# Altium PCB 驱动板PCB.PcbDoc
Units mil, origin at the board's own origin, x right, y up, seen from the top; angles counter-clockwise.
Board outline 3955.03 x 2772.03 mil, 2 copper layers (Top Layer, Bottom Layer); 5 components, 29 nets, 126 pads, 119 vias.
Unrouted connection lines stored in the file: 15.
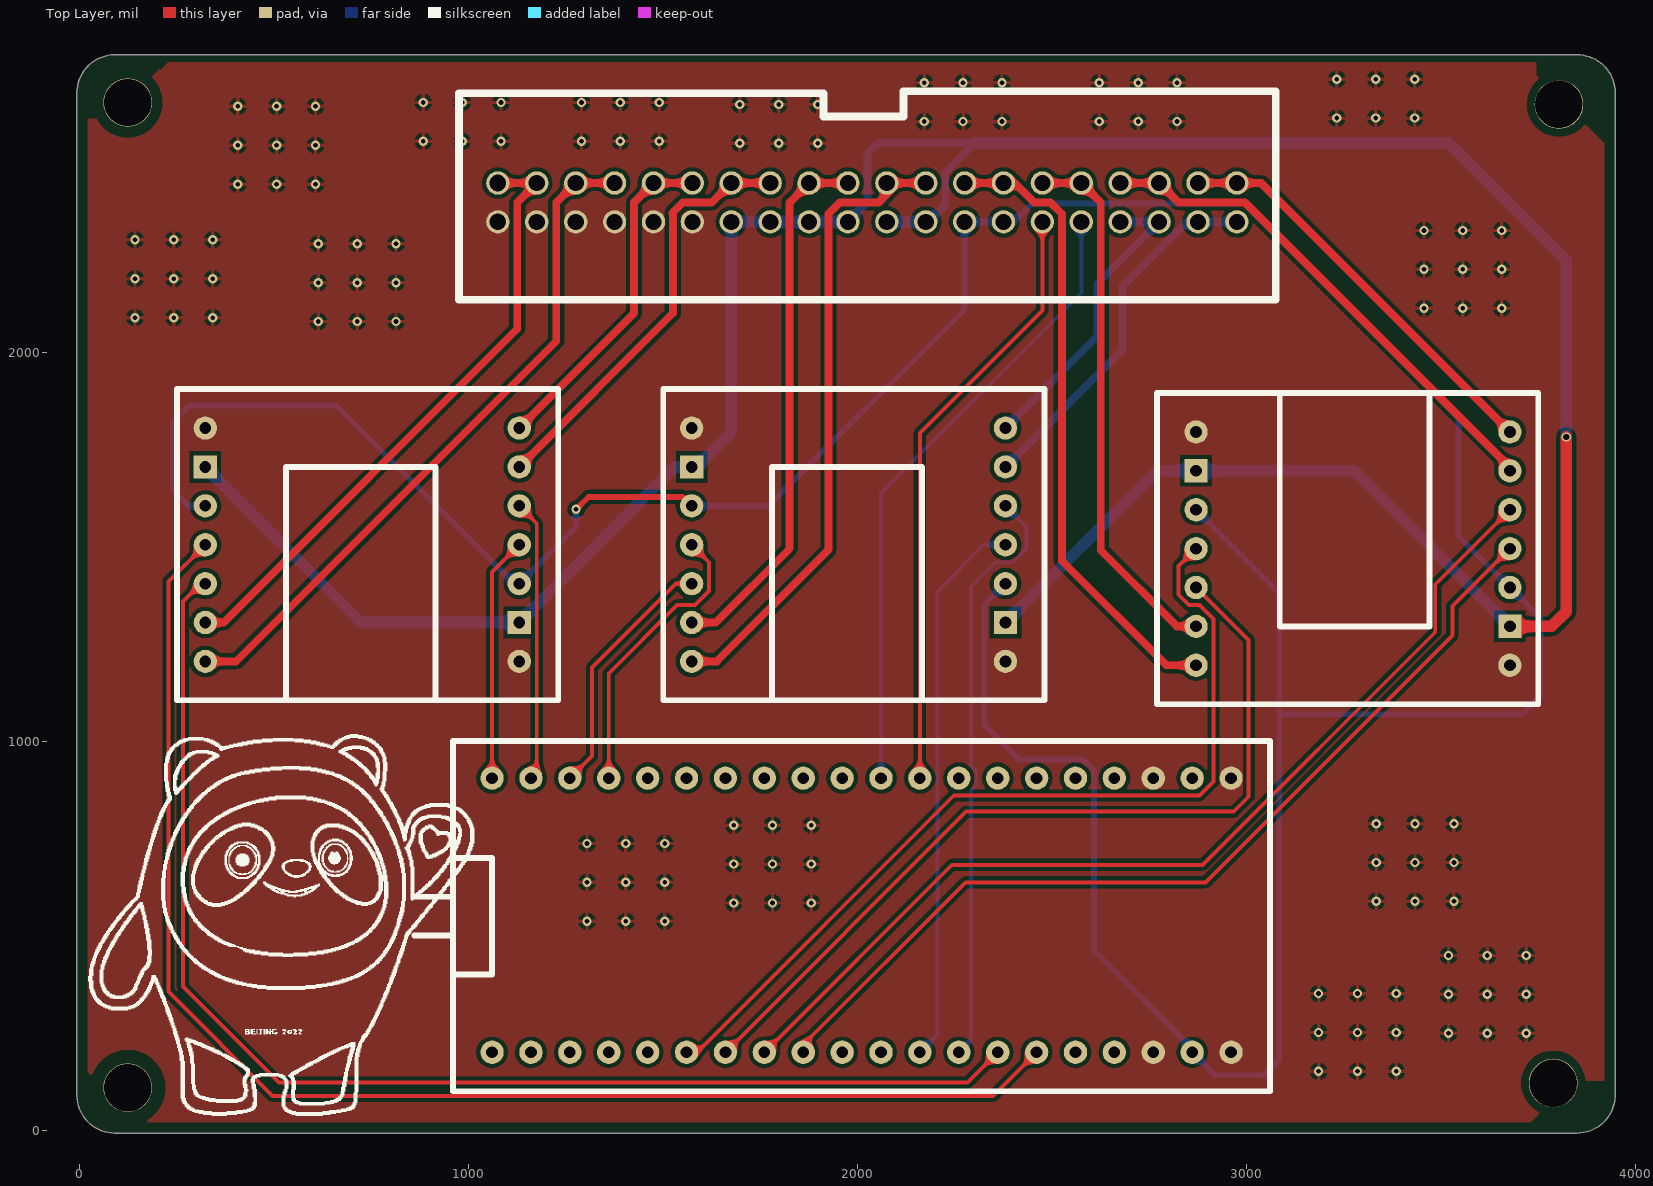
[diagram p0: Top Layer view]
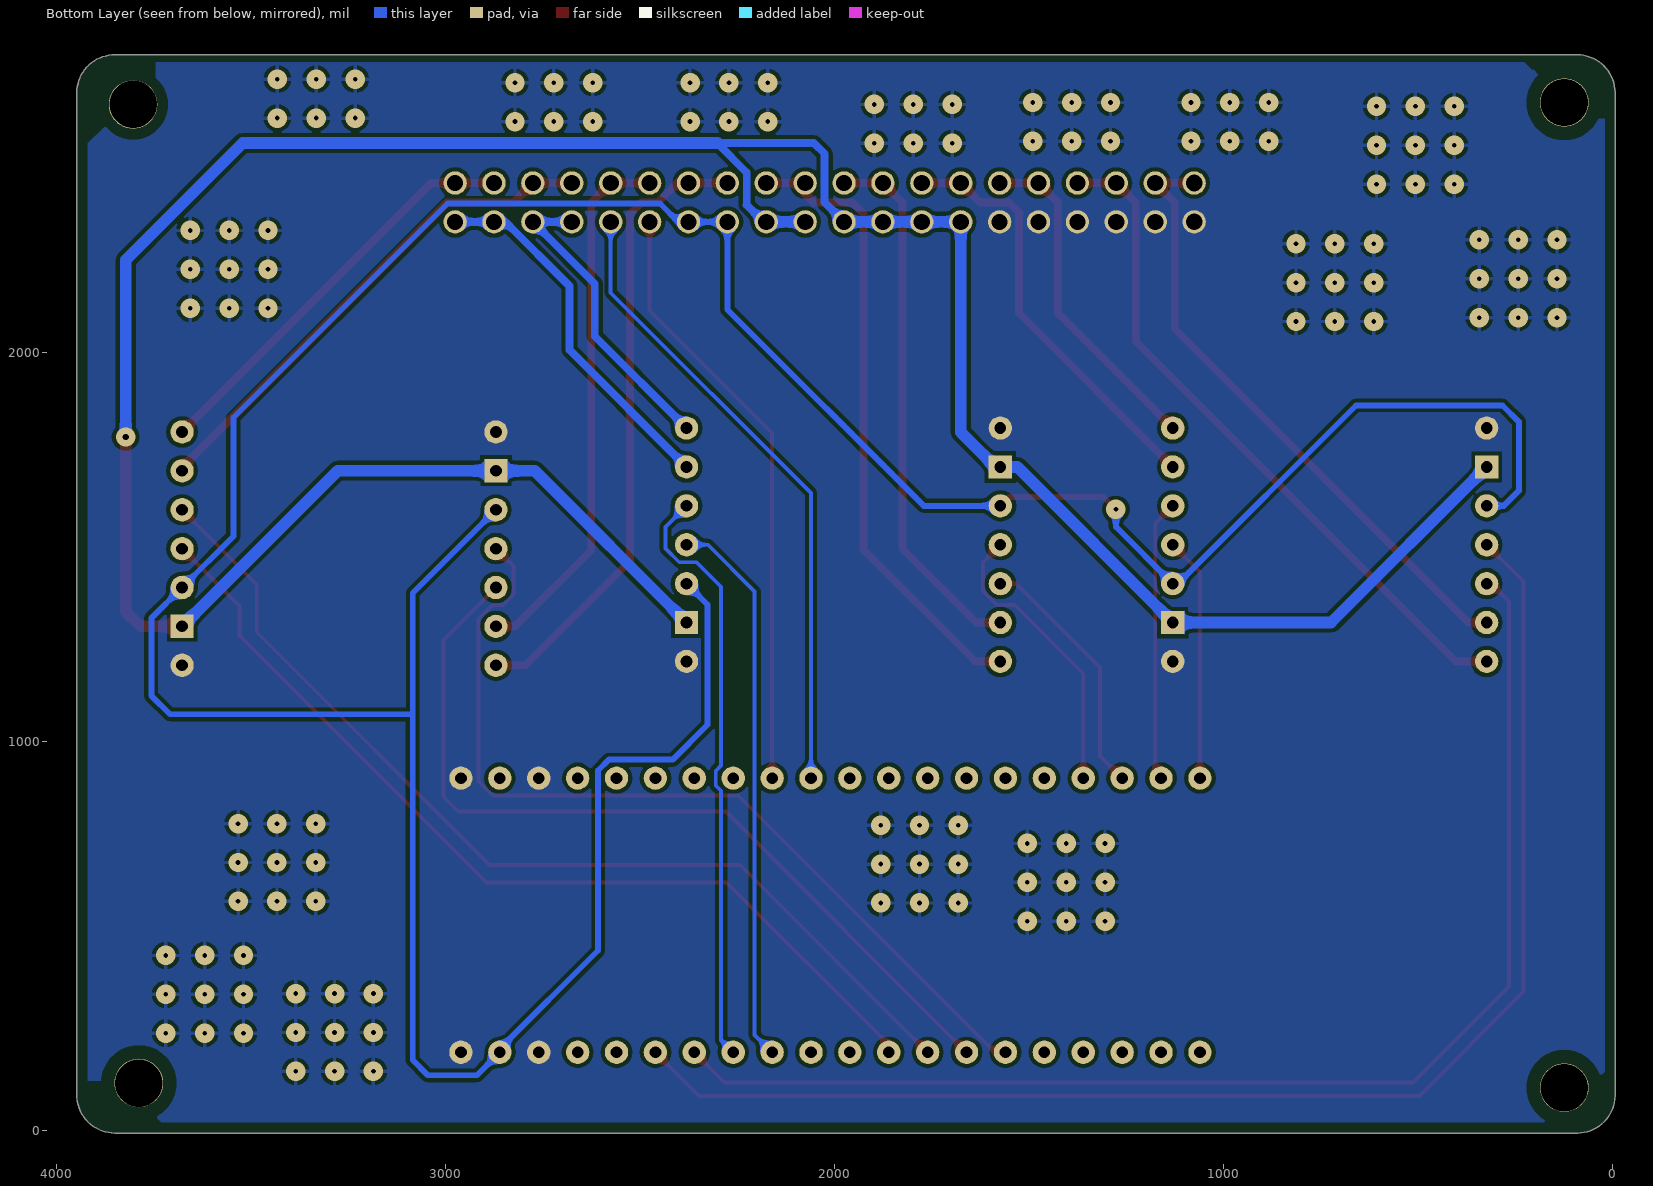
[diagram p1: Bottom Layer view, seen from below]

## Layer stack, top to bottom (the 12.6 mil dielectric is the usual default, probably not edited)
Top Solder: solder mask 0.4, Solder Resist, Dk 3.5
Top Layer: signal copper 1.4
Dielectric 1: dielectric 12.6, FR-4, Dk 4.8
Bottom Layer: signal copper 1.4
Bottom Solder: solder mask 0.4, Solder Resist, Dk 3.5

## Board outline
88.62,-7.51 cw(c90,90) -7.51,88.62 cw(c0,89) -7.51,89 -7.52,2668 cw(c0,2668) -7.51,2668.39 cw(c90,2667) 90,2764.51 cw(c90,2757) 91.68,2764.33 3848.32,2764.33 cw(c3850,2757) 3850,2764.51 cw(c3850,2667) 3947.51,2667 cw(c3940,2667) 3947.51,2666.96 3947.51,90 cw(c3850,90) 3850.04,-7.51 cw(c3850,90) 3850,-7.51 ccw(c3850,0) 3850.04,-7.51 3850,-7.51 89,-7.51 cw(c89,0)

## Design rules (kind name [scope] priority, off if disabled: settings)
Clearance [All] p1: gap=10 ignorepadtopadclearanceinfootprint=FALSE except(0: Arc-Hole Track-Hole SMDPad-Hole THPad-Hole Via-Hole Fill-Hole Poly-Hole Region-Hole Text-Hole)
HoleSize [All] p1: absolutevalues=TRUE maxlimit=150 minlimit=1 maxpercent=80.000 minpercent=20.000
PolygonConnect PolygonConnect_1 [All] p1: thpad.connectstyle=Direct thpad.reliefconductorwidth=10 thpad.reliefentries=4 thpad.polygonreliefangle="90 Angle" thpad.airgapwidth=10 smdpad.connectstyle=Relief smdpad.reliefconductorwidth=10 smdpad.reliefentries=4 smdpad.polygonreliefangle="90 Angle" smdpad.airgapwidth=10 via.connectstyle=Relief via.reliefconductorwidth=10 via.reliefentries=4 via.polygonreliefangle="90 Angle" via.airgapwidth=10
PolygonConnect [All] p2: connectstyle=Direct reliefconductorwidth=10 reliefentries=4 polygonreliefangle="90 Angle" airgapwidth=10
RoutingVias [All] p1: holewidth=28 width=50 viastyle="Through Hole" minholewidth=28 minwidth=50 maxholewidth=28 maxwidth=50
SolderMaskExpansion [All] p1: expansion=4
Width [All] p1: maxlimit=40 minlimit=10 preferedwidth=10
29 further rules are at their usual default settings.

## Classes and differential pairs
component class 驱动板原理图: ""

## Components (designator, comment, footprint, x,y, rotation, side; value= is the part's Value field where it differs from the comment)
*1 "A4950" A4950 3250,1250 r0 top
*2 "A4950" A4950 2000,1750 r180 top
*3 "A4950" A4950 750,1750 r180 top
*4 "STM32F401" STM32F401CCU6 2960,805 r90 top
*5 "40P" PCBComponent_1 2875,2435 r270 top

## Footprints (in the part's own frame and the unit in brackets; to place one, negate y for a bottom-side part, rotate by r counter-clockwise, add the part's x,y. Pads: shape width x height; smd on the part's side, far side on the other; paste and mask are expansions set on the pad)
A4950 [mil]
  round 60 hole 30: 1(-380,545) 3(-380,345) 4(-380,245) 5(-380,145) 6(-380,45) 7(-380,-55) 8(427,545) 9(427,445) 10(427,345) 11(427,245) 12(427,145) 14(427,-55)
  rect 60x60 hole 30: 2(-380,445) 13(427,45)
  silkscreen extent -480,-155 500,645
PCBComponent_1 [mil]
  round 60 hole 41.73: 1(0,100) 2(0,0) 3(0,-100) 4(0,-200) 5(0,-300) 6(0,-400) 7(0,-500) 8(0,-600) 9(0,-700) 10(0,-800) 11(0,-900) 12(0,-1000) 13(0,-1100) 14(0,-1200) 15(0,-1300) 16(0,-1400) 17(0,-1500) 18(0,-1600) 19(0,-1700) 21(100,100) 22(100,0) 23(100,-100) 24(100,-200) 25(100,-300) 26(100,-400) 27(100,-500) 28(100,-600) 29(100,-700) 30(100,-800) 31(100,-900) 32(100,-1000) 33(100,-1100) 34(100,-1200) 35(100,-1300) 36(100,-1400) 37(100,-1500) 38(100,-1600) 39(100,-1700)
  round 60 hole 42.52: 20(0,-1800) 40(100,-1800)
  silkscreen extent -236,-1900 300,200
STM32F401CCU6 [mil]
  round 60 hole 30: 1(-605,1900) 2(-605,1800) 3(-605,1700) 4(-605,1600) 5(-605,1500) 6(-605,1400) 7(-605,1300) 8(-605,1200) 9(-605,1100) 10(-605,1000) 11(-605,900) 12(-605,800) 13(-605,700) 14(-605,600) 15(-605,500) 16(-605,400) 17(-605,300) 18(-605,200) 19(-605,100) 20(-605,0) 21(100,1900) 22(100,1800) 23(100,1700) 24(100,1600) 25(100,1500) 26(100,1400) 27(100,1300) 28(100,1200) 29(100,1100) 30(100,1000) 31(100,900) 32(100,800) 33(100,700) 34(100,600) 35(100,500) 36(100,400) 37(100,300) 38(100,200) 39(100,100) 40(100,0)
  silkscreen extent -705,-100 195,2100

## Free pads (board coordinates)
  round 125 hole 122: 2(123.31,109) 2(123.31,2642) 2(3788.31,121) 2(3803,2637)

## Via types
v1: diameter 24/50 (per signal layer), hole 12, Top Layer to Bottom Layer, 118 vias
v2: diameter 24/50 (per signal layer), hole 16, Top Layer to Bottom Layer, 1 vias

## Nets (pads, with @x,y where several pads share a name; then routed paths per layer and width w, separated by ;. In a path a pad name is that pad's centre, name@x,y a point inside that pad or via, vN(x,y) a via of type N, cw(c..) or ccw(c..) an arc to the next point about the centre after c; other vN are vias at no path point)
5V: *1.3 *1.12 *2.3 *2.12 *3.3 *3.12 *4.19 *5.27 *5.28 | length 9407.8
  Top Layer w15: v1(1276,1596) 1308,1628 1550,1628 *2.12
  Bottom Layer w15: *3.12 279,1605 240,1644 240,1821 282,1863 659,1863 1117,1405 *3.3 1276,1551 v1(1276,1596) ; *2.12 1770,1605 2275,2110 *5.28 *5.27 2401,2335 2448.5,2382.5 2994.68,2382.5 3545,1832.18 3545,1527 *1.12 3756,1316 3756,1117 3708,1069 3089,1069 3084,1064 ; *2.3 2326,1351 2326,1042 2415.5,952.5 2579.68,952.5 2607.5,924.68 2607.5,461.5 2860,209 *4.19 2919,141 3045,141 3084,180 3084,1064 ; *1.3 3084,1381 3084,1064
12V: *1.2 *1.13 *2.2 *2.13 *3.2 *3.13 *5.29 *5.30 *5.31 *5.32 *5.33 *5.34 | length 7738.6
  Top Layer w30: *1.13 3784,1295 3822,1333 v2(3822,1782)
  Bottom Layer w20: *5.31 2025,2385 2025,2510 2053,2538 2300.22,2538 2300.22,2536.93 2225,2461.71 2225,2379 2225.5,2378.5 *5.29@2182,2335
  Bottom Layer w30: *3.13 723,1305 *3.2 1530,1705 *2.13 1586,1705 1675,1794 *5.34 *5.33 *5.32 *5.31 ; *5.30 *5.29 *5.29@2182,2335 ; 2300.22,2538 3521,2538 3822,2237 v2(3822,1782) ; *2.2 2770,1695 *1.2 3277,1695 *1.13
401R: *4.31 *5.25 | length 1643.3
  Bottom Layer w10: *4.31 2060,1638 2575,2153 *5.25
401T: *4.32 *5.26 | length 1560.5
  Top Layer w10: *4.32 2160,1792 2475,2107 *5.26
GND: *1.1 *1.14 *2.1 *2.14 *3.1 *3.14 *4.18 *4.20 *4.38 *4.40 *5.35 *5.36 *5.37 *5.38 *5.39 *5.40
  other v1: 3185,151 3285,151 3385,151 3519,249 3619,249 3719,249 3185,251 3285,251 3385,251 3519,349 3619,349 3719,349 3185,351 3285,351 3385,351 3519,449 3619,449 3719,449 1304,537 1404,537 1504,537 1681,584 1781,584 1881,584 3333,588 3433,588 3533,588 1304,637 1404,637 1504,637 1681,684 1781,684 1881,684 3333,688 3433,688 3533,688 1304,737 1404,737 1504,737 1681,784 1781,784 1881,784 3333,788 3433,788 3533,788 613,2079 713,2079 813,2079 142,2089 242,2089 342,2089 3456,2113 3556,2113 3656,2113 613,2179 713,2179 813,2179 142,2189 242,2189 342,2189 3456,2213 3556,2213 3656,2213 613,2279 713,2279 813,2279 142,2289 242,2289 342,2289 3456,2313 3556,2313 3656,2313 406,2432 506,2432 606,2432 406,2532 506,2532 606,2532 1697,2537 1797,2537 1897,2537 883,2542 983,2542 1083,2542 1290,2542 1390,2542 1490,2542 2171,2593 2271,2593 2371,2593 2621,2593 2721,2593 2821,2593 3232,2602 3332,2602 3432,2602 406,2632 506,2632 606,2632 1697,2637 1797,2637 1897,2637 883,2642 983,2642 1083,2642 1290,2642 1390,2642 1490,2642 2171,2693 2271,2693 2371,2693 2621,2693 2721,2693 2821,2693 3232,2702 3332,2702 3432,2702
M11: *1.4 *4.6 | length 2314.2
  Top Layer w10: *4.6 1587,200 2247,860 2878.64,860 2915,896.36 2915,1314 2879,1350 2851.36,1350 2825,1376.36 2825,1450 *1.4
M12: *1.5 *4.7 | length 2211.1
  Top Layer w10: *4.7 2279,819 2967,819 3005,857 3005,1260 *1.5
M21: *1.10 *4.8 | length 2566.9
  Top Layer w10: *4.8 2242,682 2887,682 3485,1280 3485,1403 *1.10
M22: *1.11 *4.9 | length 2409.1
  Top Layer w10: *4.9 1860,220 2277,637 2894,637 3529,1272 3529,1347 *1.11
M31: *2.4 *4.12 | length 1428.3
  Bottom Layer w10: *4.12 2205,245 2205,1385 2325,1505 *2.4
M32: *2.5 *4.13 | length 1537.2
  Bottom Layer w10: *4.13 2291,231 2291,872.36 2305,886.36 2305,923.64 2291,937.64 2291,1397 2354,1460 2398.64,1460 2434,1495.36 2434,1551 *2.5
M41: *3.10 *4.14 | length 3296.7
  Top Layer w10: *3.10 311,1405 265,1359 265,369 512,122 2282,122 *4.14
M42: *3.11 *4.15 | length 3577.8
  Top Layer w10: *3.11 228,1410 228,356 496,88 2348,88 *4.15
M51: *3.4 *4.21 | length 629
  Top Layer w10: *4.21 1060,1435 *3.4
M52: *3.5 *4.22 | length 724.9
  Top Layer w10: *3.5 1175,1560 1175,920 *4.22
M61: *2.10 *4.23 | length 653.1
  Top Layer w10: *4.23 1317,962 1317,1189 1533,1405 *2.10
M62: *2.11 *4.24 | length 752.2
  Top Layer w10: *4.24 1360,1174 1536,1350 1581.64,1350 1618,1386.36 1618,1460 *2.11
MO11: *1.8 *5.1 *5.2 | length 1067.1
  Top Layer w20: *5.2 *5.1 3037,2435 *1.8
MO12: *1.9 *5.3 *5.4 | length 1313.6
  Top Layer w20: *5.4 *5.3 2825,2385 2995.71,2385 3677,1703.71 *1.9
MO21: *1.6 *5.5 *5.6 | length 1390.9
  Top Layer w20: *5.6 *5.5 2625,2385 2625,1491 2821,1295 *1.6
MO22: *1.7 *5.7 *5.8 | length 1631
  Top Layer w20: *5.8 *5.7 2404,2435 2454,2385 2495.71,2385 2525,2355.71 2525,1464 2794,1195 *1.7
MO31: *2.8 *5.9 *5.10 | length 1634.6
  Top Layer w20: *2.8 1638,1205 1925,1492 1925,2355.71 1954.29,2385 2054.29,2385 2075,2405.71 *5.10 *5.9
MO32: *2.9 *5.11 *5.12 | length 1391.4
  Top Layer w20: *2.9 1635,1305 1825,1495 1825,2385 *5.12 *5.11
MO41: *3.6 *5.13 *5.14 | length 1100.3
  Top Layer w20: *3.6 1525,2100 1525,2355.71 1524,2356.71 1524,2358.71 1550.29,2385 1625,2385 *5.14 *5.13
MO42: *3.7 *5.15 *5.16 | length 872.9
  Top Layer w20: *3.7 1425,2100 1425,2385 *5.16 *5.15
MO51: *3.8 *5.17 *5.18 | length 1770.6
  Top Layer w20: *3.8 402,1205 1225,2028 1225,2385 *5.18 *5.17
MO52: *3.9 *5.19 *5.20 | length 1610.4
  Top Layer w20: *3.9 370,1305 1125,2060 1125,2385 *5.19 *5.20
MO61: *2.6 *5.21 *5.22 | length 952.2
  Bottom Layer w20: *2.6 2681,2006 2681,2170.29 2845.71,2335 *5.22 *5.21
MO62: *2.7 *5.23 *5.24 | length 793.6
  Bottom Layer w20: *2.7 2616,2041 2616,2176 *5.23 *5.24
pads on no net: *4.1 *4.2 *4.3 *4.4 *4.5 *4.10 *4.11 *4.16 *4.17 *4.25 *4.26 *4.27 *4.28 *4.29 *4.30 *4.33 *4.34 *4.35 *4.36 *4.37 *4.39

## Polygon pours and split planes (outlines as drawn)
GND on Bottom Layer (solid, remove dead copper, pour order 2): 206.1,2725.14 226.1,2745.14 3744.1,2745.14 3744.1,2712.14 3919.1,2537.14 3919.1,127.14 3837.1,127.14 3730.1,20.14 149.1,20.14 19.1,150.14 19.1,2600.14 76.1,2600.14 225.1,2749.14
GND on Top Layer (solid, remove dead copper, pour order 0): 207,2725 227,2745 3745,2745 3745,2712 3920,2537 3920,127 3838,127 3731,20 150,20 20,150 20,2600 77,2600 226,2749

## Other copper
Top Layer:
  pour cut-out: 3705.3,121 ccw(c3788.31,121) 3788.31,37.99 ccw(c3788.31,121) 3871.31,121 ccw(c3788.31,121) 3788.31,204.01 ccw(c3788.31,121)
  pour cut-out: 3719.99,2637 ccw(c3803,2637) 3803,2553.99 ccw(c3803,2637) 3886.01,2637 ccw(c3803,2637) 3803,2720.01 ccw(c3803,2637)
  pour cut-out: 123.31,2551.85 cw(c123.31,2642) 33.15,2642 cw(c123.31,2642) 123.31,2732.15 cw(c123.31,2642) 213.46,2642 cw(c123.31,2642)
  pour cut-out: 25.74,109 ccw(c123.31,109) 123.31,11.44 ccw(c123.31,109) 220.87,109 ccw(c123.31,109) 123.31,206.56 ccw(c123.31,109)
Bottom Layer:
  pour cut-out: 3712.85,2637 ccw(c3803,2637) 3803,2546.85 ccw(c3803,2637) 3893.15,2637 ccw(c3803,2637) 3803,2727.15 ccw(c3803,2637)
  pour cut-out: 3690.74,121 cw(c3788.31,121) 3788.31,218.56 cw(c3788.31,121) 3885.87,121 cw(c3788.31,121) 3788.31,23.44 cw(c3788.31,121)
  pour cut-out: 123.31,2544.44 cw(c123.31,2642) 25.74,2642 cw(c123.31,2642) 123.31,2739.56 cw(c123.31,2642) 220.87,2642 cw(c123.31,2642)
  pour cut-out: 25.74,109 ccw(c123.31,109) 123.31,11.44 ccw(c123.31,109) 220.87,109 ccw(c123.31,109) 123.31,206.56 ccw(c123.31,109)

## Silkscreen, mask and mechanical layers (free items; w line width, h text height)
Top Overlay:
  drawing of 3503 lines, arcs and shapes, not listed
Mechanical 1:
  lines w15: 0,89 0,2668 ; 0,90 ccw(c90,90) 90,0 ; 0,2667 cw(c90,2667) 90,2757 ; 89,0 3850,0 ccw(c3850,90) 3940,90 3940,2667 ccw(c3850,2667) 3850,2757 ; 90,2756.81 3850,2756.81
